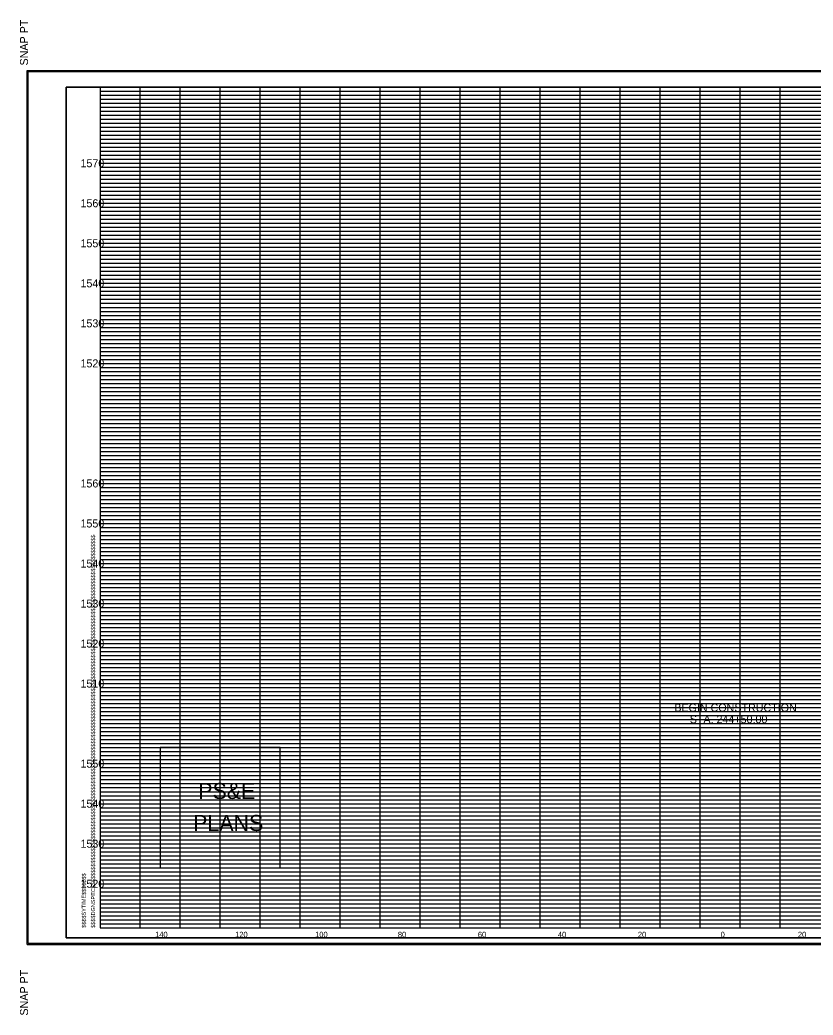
# Model space of a CAD drawing. Extents: x 955 to 1375, y 1248 to 3657.
# Drawn here: x 979.9 to 1178.2, y 1248.2 to 1496.8 of the extents above; entities that cross this region are included whole.
import ezdxf

# ---------------------------------------------------------------- set-up
doc = ezdxf.new("R2010")
doc.units = 0
for name, color, linetype in [('DESIGN - SHEET - Corner Text', 7, 'Continuous'), ('DESIGN - SHEET - Light Grid', 7, 'Continuous'), ('DESIGN - SHEET - Linework', 7, 'Continuous'), ('DESIGN - SHEET - Plot Shape', 7, 'Continuous'), ('DESIGN - TYPICAL - Text', 7, 'Continuous'), ('DESIGN - UTILITIES - Cable (Overhead) with Text', 7, 'Continuous')]:
    doc.layers.add(name, color=color, linetype=linetype)

# ---------------------------------------------------------------- blocks, each defined once
blk = doc.blocks.new('XSTSHT')
at = {"layer": 'DESIGN - SHEET - Light Grid'}
for p, q in [((0, 20.9), (8, 20.9)), ((8, 20.9), (16, 20.9)), ((16, 20.9), (24, 20.9)), ((0, 20.8), (8, 20.8)), ((0, 20.7), (8, 20.7)), ((8, 20.8), (16, 20.8)), ((8, 20.7), (16, 20.7)), ((16, 20.8), (24, 20.8)), ((16, 20.7), (24, 20.7)), ((0, 20.6), (8, 20.6)), ((0, 20.5), (8, 20.5)), ((0, 20.4), (8, 20.4)), ((8, 20.6), (16, 20.6)), ((8, 20.5), (16, 20.5)), ((8, 20.4), (16, 20.4)), ((16, 20.6), (24, 20.6)), ((16, 20.5), (24, 20.5)), ((16, 20.4), (24, 20.4)), ((0, 20.3), (8, 20.3)), ((0, 20.2), (8, 20.2)), ((8, 20.3), (16, 20.3)), ((8, 20.2), (16, 20.2)), ((16, 20.3), (24, 20.3)), ((16, 20.2), (24, 20.2)), ((0, 20.1), (8, 20.1)), ((0, 19.9), (8, 19.9)), ((8, 20.1), (16, 20.1)), ((8, 19.9), (16, 19.9)), ((16, 20.1), (24, 20.1)), ((16, 19.9), (24, 19.9)), ((0, 19.8), (8, 19.8)), ((0, 19.7), (8, 19.7)), ((8, 19.8), (16, 19.8)), ((8, 19.7), (16, 19.7)), ((16, 19.8), (24, 19.8)), ((16, 19.7), (24, 19.7)), ((0, 19.6), (8, 19.6)), ((0, 19.5), (8, 19.5)), ((0, 19.4), (8, 19.4)), ((8, 19.6), (16, 19.6)), ((8, 19.5), (16, 19.5)), ((8, 19.4), (16, 19.4)), ((16, 19.6), (24, 19.6)), ((16, 19.5), (24, 19.5)), ((16, 19.4), (24, 19.4)), ((0, 19.3), (8, 19.3)), ((0, 19.2), (8, 19.2)), ((8, 19.3), (16, 19.3)), ((8, 19.2), (16, 19.2)), ((16, 19.3), (24, 19.3)), ((16, 19.2), (24, 19.2)), ((0, 19.1), (8, 19.1)), ((0, 18.9), (8, 18.9)), ((8, 19.1), (16, 19.1)), ((8, 18.9), (16, 18.9)), ((16, 19.1), (24, 19.1)), ((16, 18.9), (24, 18.9)), ((0, 18.8), (8, 18.8)), ((0, 18.7), (8, 18.7)), ((8, 18.8), (16, 18.8)), ((8, 18.7), (16, 18.7)), ((16, 18.8), (24, 18.8)), ((16, 18.7), (24, 18.7)), ((0, 18.6), (8, 18.6)), ((0, 18.5), (8, 18.5)), ((0, 18.4), (8, 18.4)), ((8, 18.6), (16, 18.6)), ((8, 18.5), (16, 18.5)), ((8, 18.4), (16, 18.4)), ((16, 18.6), (24, 18.6)), ((16, 18.5), (24, 18.5)), ((16, 18.4), (24, 18.4)), ((0, 18.3), (8, 18.3)), ((0, 18.2), (8, 18.2)), ((8, 18.3), (16, 18.3)), ((8, 18.2), (16, 18.2)), ((16, 18.3), (24, 18.3)), ((16, 18.2), (24, 18.2)), ((0, 18.1), (8, 18.1)), ((8, 18.1), (16, 18.1)), ((16, 18.1), (24, 18.1)), ((0, 17.9), (8, 17.9)), ((0, 17.8), (8, 17.8)), ((0, 17.7), (8, 17.7)), ((8, 17.9), (16, 17.9)), ((8, 17.8), (16, 17.8)), ((8, 17.7), (16, 17.7)), ((16, 17.9), (24, 17.9)), ((16, 17.8), (24, 17.8)), ((16, 17.7), (24, 17.7)), ((0, 17.6), (8, 17.6)), ((0, 17.5), (8, 17.5)), ((8, 17.6), (16, 17.6)), ((8, 17.5), (16, 17.5)), ((16, 17.6), (24, 17.6)), ((16, 17.5), (24, 17.5)), ((0, 17.4), (8, 17.4)), ((0, 17.3), (8, 17.3)), ((0, 17.2), (8, 17.2)), ((8, 17.4), (16, 17.4)), ((8, 17.3), (16, 17.3)), ((8, 17.2), (16, 17.2)), ((16, 17.4), (24, 17.4)), ((16, 17.3), (24, 17.3)), ((16, 17.2), (24, 17.2)), ((0, 17.1), (8, 17.1)), ((8, 17.1), (16, 17.1)), ((16, 17.1), (24, 17.1)), ((0, 16.9), (8, 16.9)), ((0, 16.8), (8, 16.8)), ((0, 16.7), (8, 16.7)), ((8, 16.9), (16, 16.9)), ((8, 16.8), (16, 16.8)), ((8, 16.7), (16, 16.7)), ((16, 16.9), (24, 16.9)), ((16, 16.8), (24, 16.8)), ((16, 16.7), (24, 16.7)), ((0, 16.6), (8, 16.6)), ((0, 16.5), (8, 16.5)), ((8, 16.6), (16, 16.6)), ((8, 16.5), (16, 16.5)), ((16, 16.6), (24, 16.6)), ((16, 16.5), (24, 16.5)), ((0, 16.4), (8, 16.4)), ((0, 16.3), (8, 16.3)), ((0, 16.2), (8, 16.2)), ((8, 16.4), (16, 16.4)), ((8, 16.3), (16, 16.3)), ((8, 16.2), (16, 16.2)), ((16, 16.4), (24, 16.4)), ((16, 16.3), (24, 16.3)), ((16, 16.2), (24, 16.2)), ((0, 16.1), (8, 16.1)), ((8, 16.1), (16, 16.1)), ((16, 16.1), (24, 16.1)), ((0, 15.9), (8, 15.9)), ((0, 15.8), (8, 15.8)), ((0, 15.7), (8, 15.7)), ((8, 15.9), (16, 15.9)), ((8, 15.8), (16, 15.8)), ((8, 15.7), (16, 15.7)), ((16, 15.9), (24, 15.9)), ((16, 15.8), (24, 15.8)), ((16, 15.7), (24, 15.7)), ((0, 15.6), (8, 15.6)), ((0, 15.5), (8, 15.5)), ((8, 15.6), (16, 15.6)), ((8, 15.5), (16, 15.5)), ((16, 15.6), (24, 15.6)), ((16, 15.5), (24, 15.5)), ((0, 15.4), (8, 15.4)), ((0, 15.3), (8, 15.3)), ((0, 15.2), (8, 15.2)), ((8, 15.4), (16, 15.4)), ((8, 15.3), (16, 15.3)), ((8, 15.2), (16, 15.2)), ((16, 15.4), (24, 15.4)), ((16, 15.3), (24, 15.3)), ((16, 15.2), (24, 15.2)), ((0, 15.1), (8, 15.1)), ((8, 15.1), (16, 15.1)), ((16, 15.1), (24, 15.1)), ((0, 14.9), (8, 14.9)), ((0, 14.8), (8, 14.8)), ((0, 14.7), (8, 14.7)), ((8, 14.9), (16, 14.9)), ((8, 14.8), (16, 14.8)), ((8, 14.7), (16, 14.7)), ((16, 14.9), (24, 14.9)), ((16, 14.8), (24, 14.8)), ((16, 14.7), (24, 14.7)), ((0, 14.6), (8, 14.6)), ((0, 14.5), (8, 14.5)), ((8, 14.6), (16, 14.6)), ((8, 14.5), (16, 14.5)), ((16, 14.6), (24, 14.6)), ((16, 14.5), (24, 14.5)), ((0, 14.4), (8, 14.4)), ((0, 14.3), (8, 14.3)), ((0, 14.2), (8, 14.2)), ((8, 14.4), (16, 14.4)), ((8, 14.3), (16, 14.3)), ((8, 14.2), (16, 14.2)), ((16, 14.4), (24, 14.4)), ((16, 14.3), (24, 14.3)), ((16, 14.2), (24, 14.2)), ((0, 14.1), (8, 14.1)), ((8, 14.1), (16, 14.1)), ((16, 14.1), (24, 14.1)), ((0, 13.9), (8, 13.9)), ((0, 13.8), (8, 13.8)), ((0, 13.7), (8, 13.7)), ((8, 13.9), (16, 13.9)), ((8, 13.8), (16, 13.8)), ((8, 13.7), (16, 13.7)), ((16, 13.9), (24, 13.9)), ((16, 13.8), (24, 13.8)), ((16, 13.7), (24, 13.7)), ((0, 13.6), (8, 13.6)), ((0, 13.5), (8, 13.5)), ((8, 13.6), (16, 13.6)), ((8, 13.5), (16, 13.5)), ((16, 13.6), (24, 13.6)), ((16, 13.5), (24, 13.5)), ((0, 13.4), (8, 13.4)), ((0, 13.3), (8, 13.3)), ((0, 13.2), (8, 13.2)), ((8, 13.4), (16, 13.4)), ((8, 13.3), (16, 13.3)), ((8, 13.2), (16, 13.2)), ((16, 13.4), (24, 13.4)), ((16, 13.3), (24, 13.3)), ((16, 13.2), (24, 13.2)), ((0, 13.1), (8, 13.1)), ((8, 13.1), (16, 13.1)), ((16, 13.1), (24, 13.1)), ((0, 12.9), (8, 12.9)), ((0, 12.8), (8, 12.8)), ((0, 12.7), (8, 12.7)), ((8, 12.9), (16, 12.9)), ((8, 12.8), (16, 12.8)), ((8, 12.7), (16, 12.7)), ((16, 12.9), (24, 12.9)), ((16, 12.8), (24, 12.8)), ((16, 12.7), (24, 12.7)), ((0, 12.6), (8, 12.6)), ((0, 12.5), (8, 12.5)), ((8, 12.6), (16, 12.6)), ((8, 12.5), (16, 12.5)), ((16, 12.6), (24, 12.6)), ((16, 12.5), (24, 12.5)), ((0, 12.4), (8, 12.4)), ((0, 12.3), (8, 12.3)), ((0, 12.2), (8, 12.2)), ((8, 12.4), (16, 12.4)), ((8, 12.3), (16, 12.3)), ((8, 12.2), (16, 12.2)), ((16, 12.4), (24, 12.4)), ((16, 12.3), (24, 12.3)), ((16, 12.2), (24, 12.2)), ((0, 12.1), (8, 12.1)), ((8, 12.1), (16, 12.1)), ((16, 12.1), (24, 12.1)), ((0, 11.9), (8, 11.9)), ((0, 11.8), (8, 11.8)), ((0, 11.7), (8, 11.7)), ((8, 11.9), (16, 11.9)), ((8, 11.8), (16, 11.8)), ((8, 11.7), (16, 11.7)), ((16, 11.9), (24, 11.9)), ((16, 11.8), (24, 11.8)), ((16, 11.7), (24, 11.7)), ((0, 11.6), (8, 11.6)), ((0, 11.5), (8, 11.5)), ((8, 11.6), (16, 11.6)), ((8, 11.5), (16, 11.5)), ((16, 11.6), (24, 11.6)), ((16, 11.5), (24, 11.5)), ((0, 11.4), (8, 11.4)), ((0, 11.3), (8, 11.3)), ((0, 11.2), (8, 11.2)), ((8, 11.4), (16, 11.4)), ((8, 11.3), (16, 11.3)), ((8, 11.2), (16, 11.2)), ((16, 11.4), (24, 11.4)), ((16, 11.3), (24, 11.3)), ((16, 11.2), (24, 11.2)), ((0, 11.1), (8, 11.1)), ((8, 11.1), (16, 11.1)), ((16, 11.1), (24, 11.1)), ((0, 10.9), (8, 10.9)), ((0, 10.8), (8, 10.8)), ((0, 10.7), (8, 10.7)), ((8, 10.9), (16, 10.9)), ((8, 10.8), (16, 10.8)), ((8, 10.7), (16, 10.7)), ((16, 10.9), (24, 10.9)), ((16, 10.8), (24, 10.8)), ((16, 10.7), (24, 10.7)), ((0, 10.6), (8, 10.6)), ((0, 10.5), (8, 10.5)), ((8, 10.6), (16, 10.6)), ((8, 10.5), (16, 10.5)), ((16, 10.6), (24, 10.6)), ((16, 10.5), (24, 10.5)), ((0, 10.4), (8, 10.4)), ((0, 10.3), (8, 10.3)), ((0, 10.2), (8, 10.2)), ((8, 10.4), (16, 10.4)), ((8, 10.3), (16, 10.3)), ((8, 10.2), (16, 10.2)), ((16, 10.4), (24, 10.4)), ((16, 10.3), (24, 10.3)), ((16, 10.2), (24, 10.2)), ((0, 10.1), (8, 10.1)), ((8, 10.1), (16, 10.1)), ((16, 10.1), (24, 10.1)), ((0, 9.9), (8, 9.9)), ((0, 9.8), (8, 9.8)), ((0, 9.7), (8, 9.7)), ((8, 9.9), (16, 9.9)), ((8, 9.8), (16, 9.8)), ((8, 9.7), (16, 9.7)), ((16, 9.9), (24, 9.9)), ((16, 9.8), (24, 9.8)), ((16, 9.7), (24, 9.7)), ((0, 9.6), (8, 9.6)), ((0, 9.5), (8, 9.5)), ((8, 9.6), (16, 9.6)), ((8, 9.5), (16, 9.5)), ((16, 9.6), (24, 9.6)), ((16, 9.5), (24, 9.5)), ((0, 9.4), (8, 9.4)), ((0, 9.3), (8, 9.3)), ((0, 9.2), (8, 9.2)), ((8, 9.4), (16, 9.4)), ((8, 9.3), (16, 9.3)), ((8, 9.2), (16, 9.2)), ((16, 9.4), (24, 9.4)), ((16, 9.3), (24, 9.3)), ((16, 9.2), (24, 9.2)), ((0, 9.1), (8, 9.1)), ((8, 9.1), (16, 9.1)), ((16, 9.1), (24, 9.1)), ((0, 8.9), (8, 8.9)), ((0, 8.8), (8, 8.8)), ((8, 8.9), (16, 8.9)), ((8, 8.8), (16, 8.8)), ((16, 8.9), (24, 8.9)), ((16, 8.8), (24, 8.8)), ((0, 8.7), (8, 8.7)), ((0, 8.6), (8, 8.6)), ((0, 8.5), (8, 8.5)), ((8, 8.7), (16, 8.7)), ((8, 8.6), (16, 8.6)), ((8, 8.5), (16, 8.5)), ((16, 8.7), (24, 8.7)), ((16, 8.6), (24, 8.6)), ((16, 8.5), (24, 8.5)), ((0, 8.4), (8, 8.4)), ((0, 8.3), (8, 8.3)), ((8, 8.4), (16, 8.4)), ((8, 8.3), (16, 8.3)), ((16, 8.4), (24, 8.4)), ((16, 8.3), (24, 8.3)), ((0, 8.2), (8, 8.2)), ((0, 8.1), (8, 8.1)), ((8, 8.2), (16, 8.2)), ((8, 8.1), (16, 8.1)), ((16, 8.2), (24, 8.2)), ((16, 8.1), (24, 8.1)), ((0, 7.9), (8, 7.9)), ((0, 7.8), (8, 7.8)), ((8, 7.9), (16, 7.9)), ((8, 7.8), (16, 7.8)), ((16, 7.9), (24, 7.9)), ((16, 7.8), (24, 7.8)), ((0, 7.7), (8, 7.7)), ((0, 7.6), (8, 7.6)), ((0, 7.5), (8, 7.5)), ((8, 7.7), (16, 7.7)), ((8, 7.6), (16, 7.6)), ((8, 7.5), (16, 7.5)), ((16, 7.7), (24, 7.7)), ((16, 7.6), (24, 7.6)), ((16, 7.5), (24, 7.5)), ((0, 7.4), (8, 7.4)), ((0, 7.3), (8, 7.3)), ((8, 7.4), (16, 7.4)), ((8, 7.3), (16, 7.3)), ((16, 7.4), (24, 7.4)), ((16, 7.3), (24, 7.3)), ((0, 7.2), (8, 7.2)), ((0, 7.1), (8, 7.1)), ((8, 7.2), (16, 7.2)), ((8, 7.1), (16, 7.1)), ((16, 7.2), (24, 7.2)), ((16, 7.1), (24, 7.1)), ((0, 6.9), (8, 6.9)), ((0, 6.8), (8, 6.8)), ((8, 6.9), (16, 6.9)), ((8, 6.8), (16, 6.8)), ((16, 6.9), (24, 6.9)), ((16, 6.8), (24, 6.8)), ((0, 6.7), (8, 6.7)), ((0, 6.6), (8, 6.6)), ((0, 6.5), (8, 6.5)), ((8, 6.7), (16, 6.7)), ((8, 6.6), (16, 6.6)), ((8, 6.5), (16, 6.5)), ((16, 6.7), (24, 6.7)), ((16, 6.6), (24, 6.6)), ((16, 6.5), (24, 6.5)), ((0, 6.4), (8, 6.4)), ((0, 6.3), (8, 6.3)), ((8, 6.4), (16, 6.4)), ((8, 6.3), (16, 6.3)), ((16, 6.4), (24, 6.4)), ((16, 6.3), (24, 6.3)), ((0, 6.2), (8, 6.2)), ((0, 6.1), (8, 6.1)), ((8, 6.2), (16, 6.2)), ((8, 6.1), (16, 6.1)), ((16, 6.2), (24, 6.2)), ((16, 6.1), (24, 6.1)), ((0, 5.9), (8, 5.9)), ((0, 5.8), (8, 5.8)), ((8, 5.9), (16, 5.9)), ((8, 5.8), (16, 5.8)), ((16, 5.9), (24, 5.9)), ((16, 5.8), (24, 5.8)), ((0, 5.7), (8, 5.7)), ((0, 5.6), (8, 5.6)), ((0, 5.5), (8, 5.5)), ((8, 5.7), (16, 5.7)), ((8, 5.6), (16, 5.6)), ((8, 5.5), (16, 5.5)), ((16, 5.7), (24, 5.7)), ((16, 5.6), (24, 5.6)), ((16, 5.5), (24, 5.5)), ((0, 5.4), (8, 5.4)), ((0, 5.3), (8, 5.3)), ((8, 5.4), (16, 5.4)), ((8, 5.3), (16, 5.3)), ((16, 5.4), (24, 5.4)), ((16, 5.3), (24, 5.3)), ((0, 5.2), (8, 5.2)), ((0, 5.1), (8, 5.1)), ((8, 5.2), (16, 5.2)), ((8, 5.1), (16, 5.1)), ((16, 5.2), (24, 5.2)), ((16, 5.1), (24, 5.1)), ((0, 4.9), (8, 4.9)), ((0, 4.8), (8, 4.8)), ((8, 4.9), (16, 4.9)), ((8, 4.8), (16, 4.8)), ((16, 4.9), (24, 4.9)), ((16, 4.8), (24, 4.8)), ((0, 4.7), (8, 4.7)), ((0, 4.6), (8, 4.6)), ((0, 4.5), (8, 4.5)), ((8, 4.7), (16, 4.7)), ((8, 4.6), (16, 4.6)), ((8, 4.5), (16, 4.5)), ((16, 4.7), (24, 4.7)), ((16, 4.6), (24, 4.6)), ((16, 4.5), (24, 4.5)), ((0, 4.4), (8, 4.4)), ((0, 4.3), (8, 4.3)), ((8, 4.4), (16, 4.4)), ((8, 4.3), (16, 4.3)), ((16, 4.4), (24, 4.4)), ((16, 4.3), (24, 4.3)), ((0, 4.2), (8, 4.2)), ((0, 4.1), (8, 4.1)), ((8, 4.2), (16, 4.2)), ((8, 4.1), (16, 4.1)), ((16, 4.2), (24, 4.2)), ((16, 4.1), (24, 4.1)), ((0, 3.9), (8, 3.9)), ((0, 3.8), (8, 3.8)), ((8, 3.9), (16, 3.9)), ((8, 3.8), (16, 3.8)), ((16, 3.9), (24, 3.9)), ((16, 3.8), (24, 3.8)), ((0, 3.7), (8, 3.7)), ((0, 3.6), (8, 3.6)), ((0, 3.5), (8, 3.5)), ((8, 3.7), (16, 3.7)), ((8, 3.6), (16, 3.6)), ((8, 3.5), (16, 3.5)), ((16, 3.7), (24, 3.7)), ((16, 3.6), (24, 3.6)), ((16, 3.5), (24, 3.5)), ((0, 3.4), (8, 3.4)), ((0, 3.3), (8, 3.3)), ((8, 3.4), (16, 3.4)), ((8, 3.3), (16, 3.3)), ((16, 3.4), (24, 3.4)), ((16, 3.3), (24, 3.3)), ((0, 3.2), (8, 3.2)), ((0, 3.1), (8, 3.1)), ((8, 3.2), (16, 3.2)), ((8, 3.1), (16, 3.1)), ((16, 3.2), (24, 3.2)), ((16, 3.1), (24, 3.1)), ((0, 2.9), (8, 2.9)), ((0, 2.8), (8, 2.8)), ((8, 2.9), (16, 2.9)), ((8, 2.8), (16, 2.8)), ((16, 2.9), (24, 2.9)), ((16, 2.8), (24, 2.8)), ((0, 2.7), (8, 2.7)), ((0, 2.6), (8, 2.6)), ((0, 2.5), (8, 2.5)), ((8, 2.7), (16, 2.7)), ((8, 2.6), (16, 2.6)), ((8, 2.5), (16, 2.5)), ((16, 2.7), (24, 2.7)), ((16, 2.6), (24, 2.6)), ((16, 2.5), (24, 2.5)), ((0, 2.4), (8, 2.4)), ((0, 2.3), (8, 2.3)), ((8, 2.4), (16, 2.4)), ((8, 2.3), (16, 2.3)), ((16, 2.4), (24, 2.4)), ((16, 2.3), (24, 2.3)), ((0, 2.2), (8, 2.2)), ((0, 2.1), (8, 2.1)), ((8, 2.2), (16, 2.2)), ((8, 2.1), (16, 2.1)), ((16, 2.2), (24, 2.2)), ((16, 2.1), (24, 2.1)), ((0, 1.9), (8, 1.9)), ((0, 1.8), (8, 1.8)), ((8, 1.9), (16, 1.9)), ((8, 1.8), (16, 1.8)), ((16, 1.9), (24, 1.9)), ((16, 1.8), (24, 1.8)), ((0, 1.7), (8, 1.7)), ((0, 1.6), (8, 1.6)), ((0, 1.5), (8, 1.5)), ((8, 1.7), (16, 1.7)), ((8, 1.6), (16, 1.6)), ((8, 1.5), (16, 1.5)), ((16, 1.7), (24, 1.7)), ((16, 1.6), (24, 1.6)), ((16, 1.5), (24, 1.5)), ((0, 1.4), (8, 1.4)), ((0, 1.3), (8, 1.3)), ((8, 1.4), (16, 1.4)), ((8, 1.3), (16, 1.3)), ((16, 1.4), (24, 1.4)), ((16, 1.3), (24, 1.3)), ((0, 1.2), (8, 1.2)), ((0, 1.1), (8, 1.1)), ((8, 1.2), (16, 1.2)), ((8, 1.1), (16, 1.1)), ((16, 1.2), (24, 1.2)), ((16, 1.1), (24, 1.1)), ((0, 0.9), (8, 0.9)), ((0, 0.8), (8, 0.8)), ((8, 0.9), (16, 0.9)), ((8, 0.8), (16, 0.8)), ((16, 0.9), (24, 0.9)), ((16, 0.8), (24, 0.8)), ((0, 0.7), (8, 0.7)), ((0, 0.6), (8, 0.6)), ((0, 0.5), (8, 0.5)), ((8, 0.7), (16, 0.7)), ((8, 0.6), (16, 0.6)), ((8, 0.5), (16, 0.5)), ((16, 0.7), (24, 0.7)), ((16, 0.6), (24, 0.6)), ((16, 0.5), (24, 0.5)), ((0, 0.4), (8, 0.4)), ((0, 0.3), (8, 0.3)), ((8, 0.4), (16, 0.4)), ((8, 0.3), (16, 0.3)), ((16, 0.4), (24, 0.4)), ((16, 0.3), (24, 0.3)), ((0, 0.2), (8, 0.2)), ((0, 0.1), (8, 0.1)), ((8, 0.2), (16, 0.2)), ((8, 0.1), (16, 0.1)), ((16, 0.2), (24, 0.2)), ((16, 0.1), (24, 0.1))]:
    blk.add_line(p, q, dxfattribs=at)
at = {"layer": 'DESIGN - SHEET - Linework'}
for p, q in [((-1.823, -0.414), (-1.823, 21.414)), ((-1.823, 21.414), (32.217, 21.414)), ((1, 0), (1, 21)), ((2, 0), (2, 21)), ((3, 0), (3, 21)), ((4, 0), (4, 21)), ((5, 0), (5, 21)), ((6, 0), (6, 21)), ((7, 0), (7, 21)), ((8, 0), (8, 21)), ((9, 0), (9, 21)), ((10, 0), (10, 21)), ((11, 0), (11, 21)), ((12, 0), (12, 21)), ((13, 0), (13, 21)), ((14, 0), (14, 21)), ((15, 0), (15, 21)), ((16, 0), (16, 21)), ((17, 0), (17, 21)), ((0, 20), (28, 20)), ((0, 19), (32, 19)), ((0, 18), (32, 18)), ((0, 17), (32, 17)), ((0, 16), (32, 16)), ((0, 15), (32, 15)), ((0, 14), (32, 14)), ((0, 13), (32, 13)), ((0, 12), (32, 12)), ((0, 11), (32, 11)), ((0, 10), (32, 10)), ((0, 9), (32, 9)), ((0, 8), (32, 8)), ((0, 7), (32, 7)), ((0, 6), (32, 6)), ((0, 5), (32, 5)), ((0, 4), (32, 4)), ((0, 3), (32, 3)), ((0, 2), (32, 2)), ((0, 1), (32, 1)), ((-1.823, -0.414), (32.217, -0.414))]:
    blk.add_line(p, q, dxfattribs=at)
blk.add_lwpolyline([(0, 21), (0, 0), (32, 0), (32, 21), (0, 21)], dxfattribs=at)
at = {"layer": 'DESIGN - SHEET - Plot Shape'}
for points in [[(-1.803, 21.394), (32.197, 21.394), (32.197, -0.394), (-1.803, -0.394)], [(-0.85, 21), (32, 21), (32, -0.25), (-0.85, -0.25)]]:
    blk.add_lwpolyline(points, close=True, dxfattribs=at)
at = {"layer": 'DESIGN - SHEET - Corner Text'}
for s, height, p in [('  SNAP PT', 0.2, (-1.803, 21.394)), ('$$$$DGNSPEC$$$$$$$$$$$$$$$$$$$$$$$$$$$$$$$$$$$$$$$$$$$$$$$$$$$$$$$$$$$$$$$$$$$$$$$$$$$$$$$$$$$$$$$$$$$$$$$$$$$$$$$$$$$$$$$$$$$', 0.100002, (-0.126, 0)), ('$$$$SYTIME$$$$$$$', 0.1, (-0.358, 0)), ('SNAP PT  ', 0.2, (-1.803, -2.194))]:
    blk.add_text(s, height=height, rotation=90, dxfattribs=at).set_placement(p)

msp = doc.modelspace()

# ---------------------------------------------------------------- linework, layer by layer
at = {"layer": 'DESIGN - SHEET - Corner Text'}
msp.add_lwpolyline([(1015, 1315), (1015, 1285), (1045, 1285), (1045, 1315)], close=True, dxfattribs=at)
at = {"layer": 'DESIGN - SHEET - Plot Shape'}
msp.add_lwpolyline([(991.5, 1267.5), (1320, 1267.5), (1320, 1480), (991.5, 1480)], close=True, dxfattribs=at)

# ---------------------------------------------------------------- block references
at = {"layer": 'DESIGN - UTILITIES - Cable (Overhead) with Text', "xscale": 10, "yscale": 10}
msp.add_blockref('XSTSHT', (1000, 1270), dxfattribs=at)

# ---------------------------------------------------------------- texts
at = {"layer": 'DESIGN - SHEET - Corner Text'}
for s, p in [('PS&E', (1024.52, 1302.18)), ('PLANS', (1023.24, 1294.18))]:
    msp.add_text(s, height=4, dxfattribs=at).set_placement(p)
at = {"layer": 'DESIGN - TYPICAL - Text'}
for s, height, p in [('     1570     ', 2, (991.37, 1460)), ('     1560     ', 2, (991.37, 1450)), ('     1550     ', 2, (991.37, 1440)), ('     1540     ', 2, (991.37, 1430)), ('     1530     ', 2, (991.37, 1420)), ('     1520     ', 2, (991.37, 1410)), ('     1560     ', 2, (991.37, 1380)), ('     1550     ', 2, (991.37, 1370)), ('     1540     ', 2, (991.37, 1360)), ('     1530     ', 2, (991.37, 1350)), ('     1520     ', 2, (991.37, 1340)), ('     1510     ', 2, (991.37, 1330)), ('BEGIN CONSTRUCTION', 2, (1143.52, 1323.99)), ('STA. 244+50.00', 2, (1147.39, 1321.09)), ('     1550     ', 2, (991.37, 1310)), ('     1540     ', 2, (991.37, 1300)), ('     1530     ', 2, (991.37, 1290)), ('     1520     ', 2, (991.37, 1280)), ('     140     ', 1.4, (1011.14, 1267.6)), ('     120     ', 1.4, (1031.14, 1267.6)), ('     100     ', 1.4, (1051.14, 1267.6)), ('     80     ', 1.4, (1071.82, 1267.6)), ('     60     ', 1.4, (1091.82, 1267.6)), ('     40     ', 1.4, (1111.82, 1267.6)), ('     20     ', 1.4, (1131.82, 1267.6)), ('     0     ', 1.4, (1152.51, 1267.6)), ('     0     ', 1.4, (1152.51, 1267.6)), ('     20     ', 1.4, (1171.82, 1267.6))]:
    msp.add_text(s, height=height, dxfattribs=at).set_placement(p)

doc.saveas('drawing.dxf')
